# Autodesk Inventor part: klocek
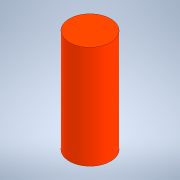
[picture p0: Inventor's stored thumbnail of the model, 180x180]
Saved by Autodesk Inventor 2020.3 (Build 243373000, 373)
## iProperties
Created: 2021-01
Part Number: klocek
Material: Ogólny
Document SubType Name: Modeling
Designer: Dom
Density: 1 g/cm^3
Appearance: Domyślna
Author: Dom
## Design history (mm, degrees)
sketch "Szkic1"
  geometry: C1 r 30 at (0, 0); 1 further point
  constraints: 1 centre point, 1 coincident
  dimensions: "d0" = 60 diameter of C1
extrude "Wyciągnięcie proste1" new body sketch "Szkic1" distance "d1" = 150; taper "d2" = 0 deg
node "Bryła1"
